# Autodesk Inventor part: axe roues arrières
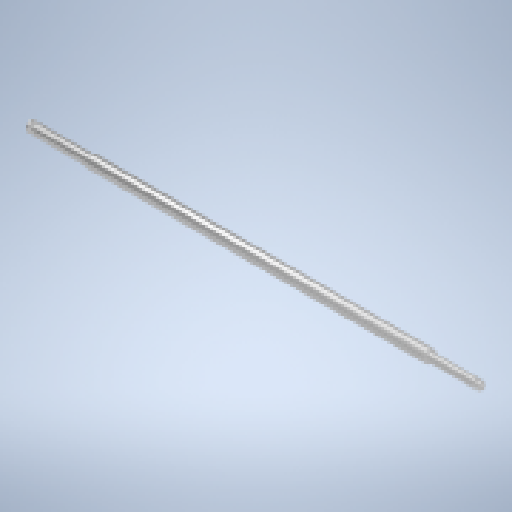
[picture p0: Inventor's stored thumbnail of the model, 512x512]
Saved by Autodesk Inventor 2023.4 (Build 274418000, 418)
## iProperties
Created: 2023-11
Part Number: axe roues arrières
Material: Aluminium 6061
Document SubType Name: Modeling
Designer: mel
Density: 2.7 g/cm^3
Appearance: Aluminium - Plat
Author: mel
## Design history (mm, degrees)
sketch "Esquisse1"
  geometry: L1 (0, 0)-(160, 0); L2 (160, 0)-(160, 3); L3 (160, 3)-(0, 3); L4 (0, 3)-(0, 0); L5 (0, 0)-(-31, 0); L6 (-31, 0)-(-31, 1); L7 (0, 2.5)-(0, 0); L8 (160, 0)-(191, 0); L9 (191, 0)-(191, 1.5); L10 (160, 2.5)-(160, 0); L11 (-27, 2.5)-(-27, 1.15); L12 (-27, 1.15)-(-29, 1.15); L13 (-29, 1.15)-(-29, 2.5); L14 (-30.134, 2.5)-(-29, 2.5); L15 (-27, 2.5)-(0, 2.5); L16 (187, 2.5)-(187, 1.15); L17 (187, 1.15)-(189, 1.15); L18 (189, 1.15)-(189, 2.5); L19 (190, 2.5)-(189, 2.5); L20 (187, 2.5)-(160, 2.5); L21 (-31, 1)-(-31, 2.5); L22 (-31, 2.5)-(-30.134, 2.5); L23 (191, 1.5)-(191, 2.5); L24 (191, 2.5)-(189, 2.5); 4 further points
  constraints: 48 end point, 10 parallel, 5 perpendicular, 3 horizontal, 2 point on line, 2 vertical
  dimensions: "d0" = 160 distance of L3.end L2.end; "d1" = 3 distance of L2.end L1.end; "d3" = 2 distance of L5.end point (-31, 2); "d5" = 1 distance of L14.start point (-31, 2); "d6" = 1 distance of L6.end point (-31, 2) (= d5); "d7" = 1 distance of L19.start L23.end (= d5); "d8" = 1 distance of L9.end L23.end (= d7); "d10" = 2 distance between parallel lines of L13 L6; "d11" = 2 distance between parallel lines of L11 L13; "d12" = 1.15 distance between parallel lines of L12 L5; "d13" = 2 distance of L17.end L16.end; "d14" = 1.15 distance between parallel lines of L17 L8; "d15" = 2 distance between parallel lines of L9 L18; "d16" = 2.5 distance between parallel lines of L15 L5; "d17" = 2.5 distance between parallel lines of L5 L14; "d18" = 27 distance between parallel lines of L4 L11; "d19" = 27 distance between parallel lines of L16 L2; "d20" = 2.5 distance between parallel lines of L20 L8; "d21" = 2.5 distance between parallel lines of L8 L24 (= d20)
revolve "Révolution1" sketch "Esquisse1" stored, may be unused: angle "d9" = 360 deg
chamfer "Chanfrein1" distance "d22" = 1; stored, may be unused: second distance "d23" = 2, angle "d24" = 45 deg
node "Solide1"
